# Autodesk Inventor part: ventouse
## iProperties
Shininess: 64.0
Length Units: 11269
Angle Units: 11279
Time Units: 11290
Mass Units: 11283
Length Display Precision: 3
Angle Display Precision: 2
Compacted: True
Part Number: ventouse
Document SubType Name: Modeling
Created: 2005-01
Material: Par défaut
Designer: David
Manufacturer: Standard
Standards Organization: Custom
Density: 0.0
Volumn: 0.0
Area: 0.0
PropertySet Name: Model Information
Control State: 0
Master: False
Checked Out: False
Author: David
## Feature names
1. Révolution1 [Revolution]
2. Congé1 [Fillet]
3. Congé2 [Fillet]
4. Congé3 [Fillet]
